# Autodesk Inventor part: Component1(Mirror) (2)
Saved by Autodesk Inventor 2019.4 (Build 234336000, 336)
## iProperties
Created: 2020-06
Part Number: Component1(Mirror) (2)
Material: Generic
Document SubType Name: Modeling
Designer: Administrator
Density: 1 g/cm^3
Appearance: Default
Title: Component1(Mirror) (2)
Author: Administrator
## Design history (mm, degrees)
